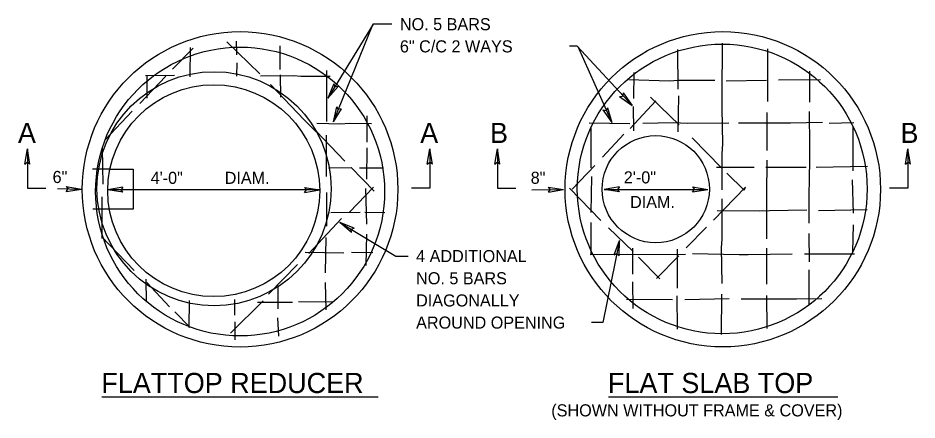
# Model space of a CAD drawing. Extents: x 26.41 to 33.74, y 20.66 to 30.6.
# Drawn here: x 29.074 to 33.531, y 28.606 to 30.601 of the extents above; entities that cross this region are included whole.
import ezdxf

# ---------------------------------------------------------------- set-up
doc = ezdxf.new("R2010")
doc.units = 0
for name, color, linetype in [('DETL-DIMS', 7, 'Continuous'), ('DETL-LINE', 7, 'Continuous'), ('DETL-NOTE', 7, 'Continuous'), ('DETL-TITL', 7, 'Continuous')]:
    doc.layers.add(name, color=color, linetype=linetype)

msp = doc.modelspace()

# ---------------------------------------------------------------- linework, layer by layer
at = {"layer": 'DETL-DIMS'}
for p, q in [((30.8353, 30.5694), (30.6105, 30.2036)), ((30.833, 30.5694), (30.637, 30.0855)), ((30.9281, 30.57), (30.8353, 30.5694)), ((31.847, 30.461), (31.8077, 30.461)), ((31.847, 30.461), (32.1186, 30.1671)), ((31.8488, 30.46), (32.0182, 30.0824)), ((30.6393, 30.2745), (30.6105, 30.2036)), ((30.6393, 30.2745), (30.6105, 30.2036)), ((30.6393, 30.2745), (30.6451, 30.2599)), ((30.6393, 30.2745), (30.6451, 30.2599)), ((30.6607, 30.2613), (30.6105, 30.2036)), ((30.6607, 30.2613), (30.6105, 30.2036)), ((30.6607, 30.2613), (30.6451, 30.2599)), ((30.6607, 30.2613), (30.6451, 30.2599)), ((32.0739, 30.2293), (32.0718, 30.2136)), ((32.0739, 30.2293), (32.1186, 30.1671)), ((32.0562, 30.2114), (32.0718, 30.2136)), ((32.0562, 30.2114), (32.1186, 30.1671)), ((30.6537, 30.1602), (30.637, 30.0855)), ((30.677, 30.1507), (30.637, 30.0855)), ((30.6537, 30.1602), (30.6618, 30.1467)), ((30.677, 30.1507), (30.6618, 30.1467)), ((31.9742, 30.1451), (32.0182, 30.0824)), ((31.9742, 30.1451), (31.9897, 30.142)), ((31.9969, 30.1559), (31.9897, 30.142)), ((31.9969, 30.1559), (32.0182, 30.0824)), ((29.107, 29.8758), (29.1205, 29.9511)), ((29.1322, 29.8755), (29.1205, 29.9511)), ((31.1034, 29.8755), (31.1151, 29.9511)), ((31.1286, 29.8758), (31.1151, 29.9511)), ((31.4373, 29.8758), (31.4508, 29.9511)), ((31.4624, 29.8755), (31.4508, 29.9511)), ((33.4742, 29.8755), (33.4858, 29.9511)), ((33.4994, 29.8758), (33.4858, 29.9511)), ((29.107, 29.8758), (29.1197, 29.8851)), ((29.1322, 29.8755), (29.1197, 29.8851)), ((31.1034, 29.8755), (31.1159, 29.8851)), ((31.1286, 29.8758), (31.1159, 29.8851)), ((31.4373, 29.8758), (31.45, 29.8851)), ((31.4624, 29.8755), (31.45, 29.8851)), ((33.4742, 29.8755), (33.4867, 29.8851)), ((33.4994, 29.8758), (33.4867, 29.8851)), ((29.2704, 29.7543), (29.3883, 29.751)), ((29.3125, 29.7405), (29.3223, 29.7528)), ((29.3125, 29.7405), (29.3883, 29.751)), ((29.3132, 29.7656), (29.3883, 29.751)), ((29.3132, 29.7656), (29.3223, 29.7528)), ((29.5943, 29.7615), (29.5189, 29.7483)), ((29.5945, 29.7363), (29.5189, 29.7483)), ((30.5699, 29.7483), (29.5189, 29.7483)), ((29.5943, 29.7615), (29.585, 29.7488)), ((29.5945, 29.7363), (29.585, 29.7488)), ((30.4944, 29.7604), (30.5699, 29.7483)), ((30.4944, 29.7604), (30.5039, 29.7479)), ((30.4945, 29.7352), (30.5699, 29.7483)), ((30.4945, 29.7352), (30.5039, 29.7479)), ((31.6208, 29.7481), (31.7789, 29.7494)), ((31.7033, 29.7614), (31.7789, 29.7494)), ((31.7033, 29.7614), (31.7129, 29.7489)), ((31.7036, 29.7362), (31.7789, 29.7494)), ((31.7036, 29.7362), (31.7129, 29.7489)), ((32.0554, 29.7634), (31.9799, 29.7508)), ((31.9799, 29.7508), (32.4933, 29.7507)), ((32.0554, 29.7382), (31.9799, 29.7508)), ((32.0554, 29.7634), (32.0459, 29.7508)), ((32.0554, 29.7382), (32.0459, 29.7508)), ((32.4179, 29.7633), (32.4933, 29.7507)), ((32.4179, 29.7633), (32.4273, 29.7507)), ((32.4179, 29.7381), (32.4933, 29.7507)), ((32.4179, 29.7381), (32.4273, 29.7507)), ((30.669, 29.586), (30.9468, 29.4199)), ((30.7273, 29.5365), (30.669, 29.586)), ((30.7402, 29.5581), (30.669, 29.586)), ((30.7402, 29.5581), (30.7256, 29.5521)), ((30.7273, 29.5365), (30.7256, 29.5521)), ((32.0565, 29.4976), (31.9735, 29.0898)), ((32.0291, 29.4262), (32.0565, 29.4976)), ((32.0538, 29.4212), (32.0565, 29.4976)), ((30.9468, 29.4199), (31.0084, 29.4197)), ((32.0291, 29.4262), (32.0434, 29.4329)), ((32.0538, 29.4212), (32.0434, 29.4329)), ((31.9735, 29.0898), (31.9171, 29.0897))]:
    msp.add_line(p, q, dxfattribs=at)
for points in [[(29.1205, 29.9511), (29.1205, 29.7562), (29.2113, 29.7562)], [(31.1151, 29.9511), (31.1151, 29.7562), (31.0243, 29.7562)], [(31.4508, 29.9511), (31.4508, 29.7562), (31.5416, 29.7562)], [(33.4858, 29.9511), (33.4858, 29.7562), (33.395, 29.7562)]]:
    msp.add_lwpolyline(points, dxfattribs=at)
at = {"layer": 'DETL-LINE'}
for p, q in [((29.84, 30.3474), (29.9427, 30.4518)), ((29.9278, 30.3095), (29.9286, 30.4544)), ((30.1099, 30.4826), (30.2726, 30.3238)), ((30.1595, 30.4182), (30.1579, 30.4855)), ((30.3737, 30.3459), (30.3735, 30.4626)), ((32.5657, 30.2162), (32.5668, 30.4765)), ((32.7907, 30.4474), (32.7901, 30.1866)), ((32.3441, 30.4439), (32.346, 30.2485)), ((30.1584, 30.3118), (30.1611, 30.3781)), ((29.6773, 30.1772), (29.8064, 30.3127)), ((29.7053, 30.316), (29.8503, 30.3171)), ((29.714, 30.2029), (29.7138, 30.3168)), ((30.2757, 30.3138), (30.4409, 30.315)), ((30.3731, 30.3182), (30.3753, 30.2075)), ((30.4409, 30.315), (30.4766, 30.3129)), ((30.4766, 30.3129), (30.6215, 30.3117)), ((30.6055, 30.087), (30.6046, 30.3397)), ((32.1268, 30.3307), (32.1258, 30.2013)), ((32.9994, 30.1837), (32.9995, 30.3371)), ((30.3266, 30.271), (30.4932, 30.0962)), ((32.1022, 30.2959), (32.3021, 30.2889)), ((32.3021, 30.2889), (32.3487, 30.2923)), ((32.3487, 30.2923), (32.5285, 30.2927)), ((32.5849, 30.2888), (32.7855, 30.2931)), ((32.8448, 30.2934), (33.0533, 30.2952)), ((32.1089, 30.0525), (32.2371, 30.1899)), ((32.2102, 30.2083), (32.3516, 30.0701)), ((32.3486, 30.2142), (32.3458, 30.0358)), ((32.5654, 30.1541), (32.5657, 30.2162)), ((29.5068, 29.9959), (29.6403, 30.1393)), ((32.1246, 30.1618), (32.1252, 30.0418)), ((32.5677, 29.9771), (32.5654, 30.1541)), ((32.9999, 29.962), (32.999, 30.1362)), ((30.4932, 30.0962), (30.5528, 30.0357)), ((30.8042, 30.1158), (30.8041, 29.9854)), ((32.7871, 30.1321), (32.7859, 29.9429)), ((30.555, 30.0785), (30.6745, 30.0758)), ((30.6745, 30.0758), (30.7164, 30.0798)), ((30.7164, 30.0798), (30.8274, 30.0777)), ((32.1079, 30.0765), (31.9066, 30.0788)), ((31.9133, 30.0594), (31.9146, 29.8579)), ((32.3245, 30.08), (32.172, 30.0781)), ((32.3941, 30.0778), (32.3245, 30.08)), ((32.5979, 30.0791), (32.3941, 30.0778)), ((32.8577, 30.079), (32.6468, 30.0792)), ((32.9033, 30.0787), (32.8577, 30.079)), ((33.062, 30.0818), (32.9033, 30.0787)), ((33.2172, 30.0804), (33.0957, 30.077)), ((33.2127, 30.0644), (33.2127, 29.8432)), ((30.5528, 30.0391), (30.694, 29.89)), ((30.6041, 29.8141), (30.6038, 30.0192)), ((31.9711, 29.9096), (32.0778, 30.0239)), ((32.4158, 30.0058), (32.5622, 29.8577)), ((29.4956, 29.7758), (29.4933, 29.9556)), ((30.803, 29.9567), (30.8015, 29.8019)), ((32.5658, 29.9263), (32.5677, 29.9771)), ((32.9999, 29.9135), (32.9999, 29.962)), ((32.5653, 29.7484), (32.5658, 29.9263)), ((32.9984, 29.7856), (32.9999, 29.9135)), ((31.8209, 29.7519), (31.9341, 29.8684)), ((32.7859, 29.895), (32.7855, 29.7227)), ((29.5297, 29.8502), (29.4436, 29.8502)), ((30.7292, 29.8574), (30.6129, 29.8553)), ((30.7254, 29.8593), (30.8399, 29.7419)), ((30.8863, 29.8559), (30.7673, 29.8562)), ((32.7231, 29.8584), (32.5363, 29.8591)), ((32.5875, 29.8318), (32.6735, 29.7464)), ((32.981, 29.8588), (32.782, 29.8583)), ((33.2861, 29.8645), (33.0319, 29.8588)), ((31.9166, 29.8146), (31.9133, 29.6358)), ((32.9961, 29.7367), (32.9984, 29.7856)), ((33.2105, 29.7972), (33.2139, 29.6328)), ((30.6051, 29.5688), (30.6045, 29.735)), ((30.8361, 29.7613), (30.718, 29.6383)), ((30.7964, 29.7554), (30.8025, 29.5788)), ((31.9629, 29.5968), (31.8087, 29.7559)), ((32.6803, 29.7618), (32.5229, 29.5982)), ((32.6735, 29.7464), (32.6803, 29.7618)), ((32.9965, 29.5837), (32.9961, 29.7367)), ((29.4914, 29.5062), (29.4907, 29.7138)), ((32.5644, 29.5042), (32.5644, 29.7037)), ((32.7855, 29.7227), (32.7849, 29.6634)), ((29.5269, 29.6526), (29.4453, 29.6526)), ((32.5412, 29.6463), (32.752, 29.6447)), ((32.752, 29.6447), (32.8005, 29.6462)), ((32.7849, 29.6634), (32.7847, 29.5048)), ((32.8005, 29.6462), (32.9855, 29.6484)), ((33.0429, 29.6459), (33.2835, 29.6504)), ((30.5155, 29.4321), (30.6778, 29.6061)), ((30.6247, 29.6358), (30.7706, 29.6373)), ((30.7937, 29.6369), (30.893, 29.636)), ((31.9137, 29.5869), (31.9135, 29.4255)), ((32.1242, 29.4418), (32.0012, 29.5594)), ((32.4874, 29.5635), (32.3862, 29.4604)), ((33.2142, 29.574), (33.2113, 29.4413)), ((29.6503, 29.348), (29.4883, 29.5171)), ((30.5984, 29.3369), (30.6012, 29.512)), ((30.8011, 29.528), (30.7982, 29.3737)), ((32.9976, 29.3912), (32.9965, 29.5319)), ((32.5627, 29.4614), (32.5644, 29.5042)), ((30.6896, 29.4345), (30.4981, 29.4367)), ((30.8327, 29.4357), (30.7273, 29.4371)), ((32.0952, 29.4268), (31.9107, 29.4255)), ((32.1483, 29.4267), (32.0952, 29.4268)), ((32.1212, 29.4593), (32.1207, 29.3303)), ((32.3827, 29.4271), (32.1483, 29.4267)), ((32.3501, 29.4202), (32.2393, 29.3078)), ((32.3423, 29.4532), (32.3424, 29.2603)), ((32.6491, 29.4259), (32.4181, 29.4302)), ((32.5645, 29.2844), (32.5627, 29.4614)), ((32.6933, 29.426), (32.6491, 29.4259)), ((32.9122, 29.429), (32.6933, 29.426)), ((32.7847, 29.4582), (32.7842, 29.2803)), ((33.2218, 29.4284), (32.9729, 29.4288)), ((30.4603, 29.3781), (30.3159, 29.2302)), ((32.2558, 29.3071), (32.151, 29.4149)), ((32.9973, 29.1789), (32.9968, 29.3512)), ((29.707, 29.306), (29.709, 29.1911)), ((29.8248, 29.1687), (29.7123, 29.288)), ((30.6024, 29.1529), (30.5989, 29.288)), ((32.1213, 29.2922), (32.1217, 29.1599)), ((30.3624, 29.2745), (30.363, 29.1573)), ((29.9219, 29.1989), (29.9203, 29.0658)), ((30.2894, 29.1982), (30.1278, 29.0374)), ((30.1488, 29.1274), (30.1497, 29.2046)), ((32.091, 29.2061), (32.3197, 29.2047)), ((32.3412, 29.2222), (32.3423, 29.0565)), ((32.3809, 29.204), (32.5993, 29.2094)), ((32.5611, 29.0308), (32.5635, 29.2303)), ((32.6586, 29.2083), (32.8868, 29.2073)), ((32.785, 29.2248), (32.7862, 29.0605)), ((32.8868, 29.2073), (32.9334, 29.207)), ((32.9334, 29.207), (33.0586, 29.2098)), ((30.4346, 29.1889), (30.2615, 29.1902)), ((30.631, 29.1919), (30.4653, 29.1935)), ((29.9269, 29.0656), (29.8507, 29.1433)), ((30.3607, 29.1131), (30.3661, 29.0222)), ((30.1502, 29.0036), (30.15, 29.0935))]:
    msp.add_line(p, q, dxfattribs=at)
msp.add_lwpolyline([(29.5297, 29.8502), (29.6452, 29.8502), (29.6452, 29.6526), (29.5269, 29.6526)], dxfattribs=at)
for centre, radius in [((30.1749, 29.7507), 0.7824), ((32.5684, 29.7512), 0.7819), ((30.1752, 29.7399), 0.7165), ((32.5655, 29.7527), 0.7184), ((30.0462, 29.7538), 0.5806), ((30.0444, 29.7442), 0.5255), ((32.2359, 29.7515), 0.2659)]:
    msp.add_circle(centre, radius, dxfattribs=at)
at = {"layer": 'DETL-TITL'}
for p, q in [((29.49, 28.7216), (30.8604, 28.7216)), ((32.0022, 28.7216), (33.1385, 28.7216))]:
    msp.add_line(p, q, dxfattribs=at)

# ---------------------------------------------------------------- texts
at = {"layer": 'DETL-NOTE'}
for s, height, p in [('NO. 5 BARS', 0.05998, (30.9674, 30.54)), ('6" C/C 2 WAYS', 0.05998, (30.9674, 30.43)), ('A', 0.1, (29.0736, 29.9806)), ('A', 0.1, (31.0682, 29.9806)), ('B', 0.1, (31.4141, 29.9806)), ('B', 0.1, (33.4491, 29.9806)), ('6"', 0.05998, (29.2454, 29.7821)), ('4\'-0"', 0.05998, (29.7316, 29.7778)), ('DIAM.', 0.05998, (30.0987, 29.7778)), ('8"', 0.05998, (31.6159, 29.7782)), ('2\'-0"', 0.05998, (32.0774, 29.7802)), ('DIAM.', 0.05998, (32.1084, 29.6582)), ('4 ADDITIONAL', 0.05998, (31.0478, 29.3897)), ('NO. 5 BARS', 0.05998, (31.0478, 29.2797)), ('DIAGONALLY', 0.05998, (31.0478, 29.1697)), ('AROUND OPENING', 0.05998, (31.0478, 29.0598)), ('(SHOWN WITHOUT FRAME & COVER)', 0.05998, (31.718, 28.6245))]:
    msp.add_text(s, height=height, dxfattribs=at).set_placement(p)
at = {"layer": 'DETL-TITL'}
for s, p in [('FLATTOP REDUCER', (29.4872, 28.7402)), ('FLAT SLAB TOP', (31.9988, 28.7402))]:
    msp.add_text(s, height=0.099994, dxfattribs=at).set_placement(p)

doc.saveas('drawing.dxf')
